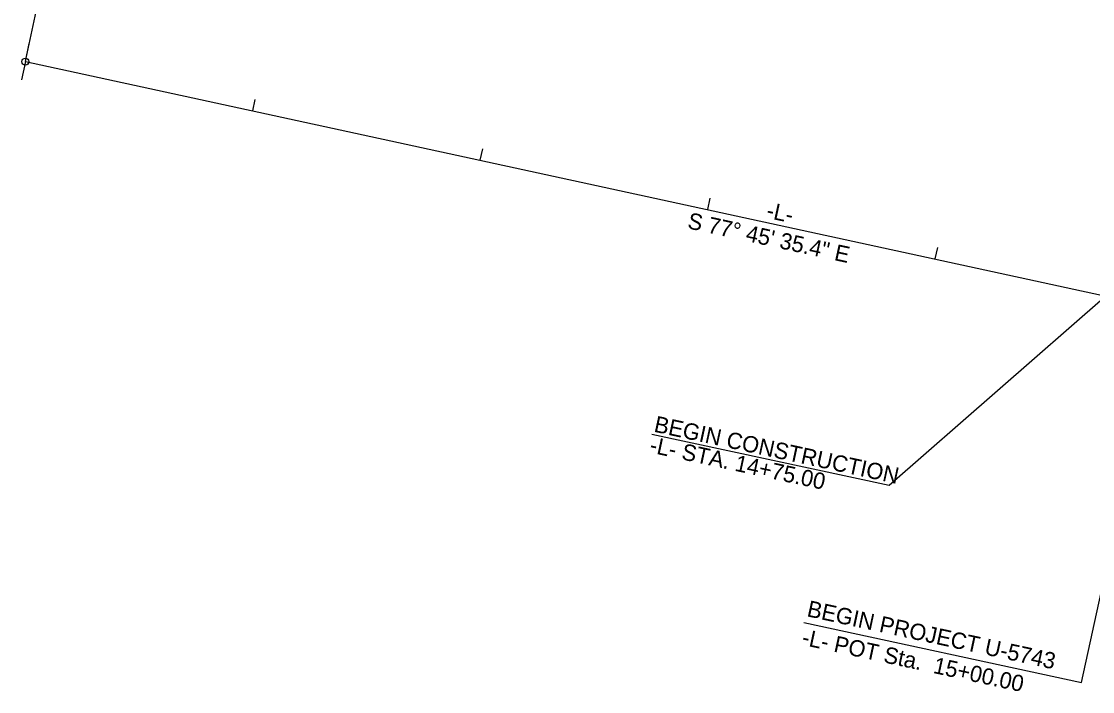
# Model space of a CAD drawing. Extents: x 1762196 to 1766326, y 709922 to 713142.
# Drawn here: x 1762195.8 to 1762656, y 712497.3 to 712785.3 of the extents above; entities that cross this region are included whole.
import ezdxf

# ---------------------------------------------------------------- set-up
doc = ezdxf.new("R2010")
doc.units = 0
for name, color, linetype in [('Old_Level_3', 7, 'Continuous'), ('Prop Horizontal Alignment', 7, 'Continuous'), ('Prop Horizontal Alignment Direction Label', 7, 'Continuous'), ('Prop Horizontal Alignment Station Label', 7, 'Continuous'), ('Prop Horizontal Alignment Tick Large', 7, 'Continuous'), ('Prop Horizontal Alignment Tick Small', 7, 'Continuous')]:
    doc.layers.add(name, color=color, linetype=linetype)

msp = doc.modelspace()

# ---------------------------------------------------------------- linework, layer by layer
at = {"layer": 'Old_Level_3'}
msp.add_line((1762221.98, 712762.66), (1762221.98, 712762.66), dxfattribs=at)
at = {"layer": 'Prop Horizontal Alignment'}
msp.add_line((1762197.55, 712767.96), (1763046.05, 712583.89), dxfattribs=at)
at = {"layer": 'Prop Horizontal Alignment Station Label'}
for p, q in [((1762197.86, 712769.43), (1762244.63, 712985.01)), ((1762568.58, 712585.93), (1762661.75, 712667.26)), ((1762651.31, 712501.23), (1762686.18, 712661.96)), ((1762466.7, 712607.84), (1762568.58, 712585.93)), ((1762531.98, 712526.89), (1762651.31, 712501.23))]:
    msp.add_line(p, q, dxfattribs=at)
msp.add_circle((1762197.55, 712767.96), 1.5, dxfattribs=at)
at = {"layer": 'Prop Horizontal Alignment Tick Large'}
for q in [(1762199.24, 712775.78), (1762195.85, 712760.14)]:
    msp.add_line((1762197.55, 712767.96), q, dxfattribs=at)
at = {"layer": 'Prop Horizontal Alignment Tick Small'}
for p, q in [((1762295.27, 712746.76), (1762296.33, 712751.65)), ((1762393, 712725.56), (1762394.06, 712730.45)), ((1762490.73, 712704.36), (1762491.79, 712709.25)), ((1762588.45, 712683.16), (1762589.51, 712688.04))]:
    msp.add_line(p, q, dxfattribs=at)

# ---------------------------------------------------------------- texts
at = {"layer": 'Prop Horizontal Alignment Direction Label'}
for s, rotation, p in [('-L-', 347.8638, (1762515.49, 712700.93)), ('S 77%%d 45\' 35.4" E', 347.7598, (1762481.63, 712696.41))]:
    msp.add_text(s, height=7, rotation=rotation, dxfattribs=at).set_placement(p)
at = {"layer": 'Prop Horizontal Alignment Station Label'}
for s, p in [('BEGIN CONSTRUCTION', (1762467.24, 712608.99)), ('-L- STA. 14+75.00', (1762465.33, 712600.09)), ('BEGIN PROJECT U-5743', (1762532.97, 712529.68)), ('-L- POT Sta.  15+00.00', (1762530.74, 712517.45))]:
    msp.add_text(s, height=7, rotation=347.8638, dxfattribs=at).set_placement(p)

doc.saveas('drawing.dxf')
